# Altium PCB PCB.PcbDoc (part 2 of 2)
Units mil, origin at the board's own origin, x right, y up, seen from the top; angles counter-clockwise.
Board outline 1141.73 x 1220.47 mil, 2 copper layers (Top Layer, Bottom Layer), stack 61.8 mil thick; 114 components, 66 nets, 300 pads, 104 vias.
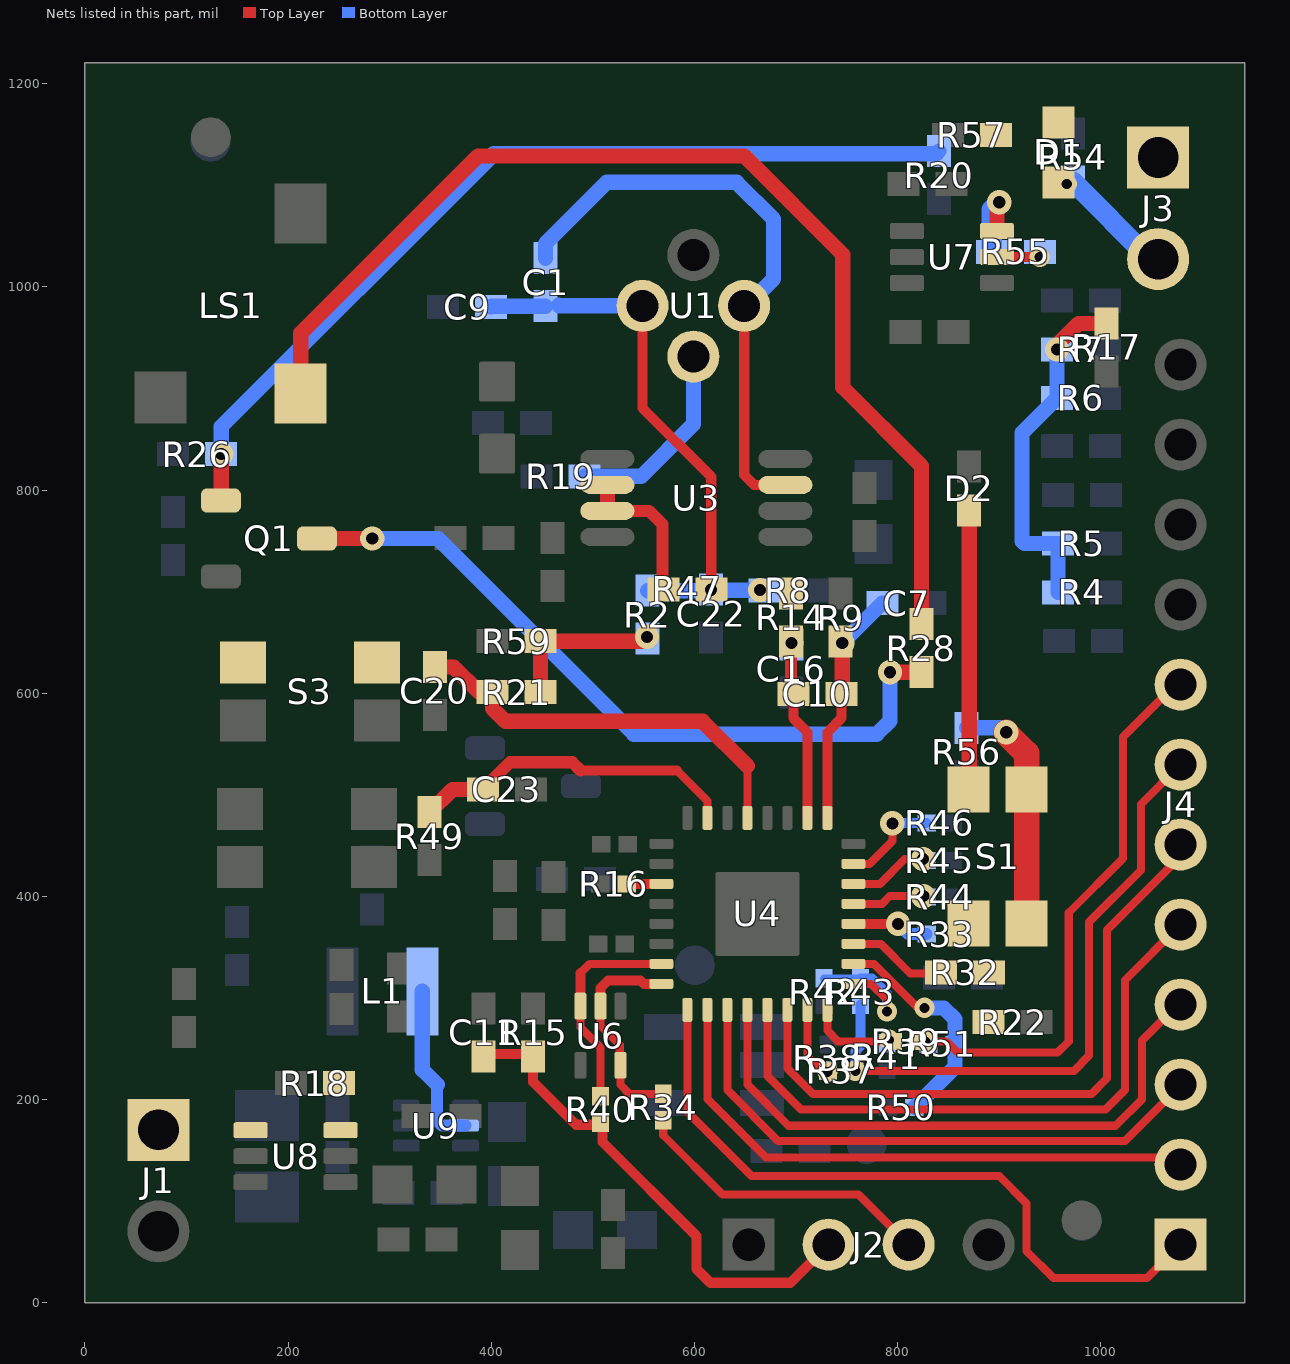
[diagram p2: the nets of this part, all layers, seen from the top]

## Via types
v1: diameter 24, hole 12, Top Layer to Bottom Layer, 83 vias
v2: diameter 20, hole 10, Top Layer to Bottom Layer, 9 vias
v3: diameter 40, hole 20, Top Layer to Bottom Layer, 6 vias
v4: diameter 19.68, hole 7.87, Top Layer to Bottom Layer, 5 vias
v5: diameter 24, hole 15, Top Layer to Bottom Layer, 1 vias

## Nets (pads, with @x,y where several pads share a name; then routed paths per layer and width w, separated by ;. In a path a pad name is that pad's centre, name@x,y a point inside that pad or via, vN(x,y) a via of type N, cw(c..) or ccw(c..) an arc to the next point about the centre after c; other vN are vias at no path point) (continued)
NetD1_1: D1.1 J3.1 R55.2 R57.1 U7.6 | length 81.3
  Top Layer w15: U7.6@897.66,1054.98 897.66,1081.08 v1(899.95,1083.36)
  Bottom Layer w20: R55.2@892.63,1034.39 892.63,1076.04 v1(899.95,1083.36)
NetD1_2: D1.2 J3.2 R54.2 | length 115.6
  Bottom Layer w20: R54.2@972.37,1103.77 1048.75,1027.39 J3.2@1056.37,1027.39
  other v2: 966.41,1101.37
NetJ1_1: J1.1 U8.1
NetL1_1: L1.1 U9.5 | length 163.4
  Bottom Layer w11.8: 346.75,214.87 346.75,179.03 351.39,174.39 U9.5@374.5,174.39
  Bottom Layer w15: L1.1@332.12,306.74 332.12,229.51 346.75,214.87
NetLS1_1: LS1.1 R28.1 | length 1081.1
  Top Layer w15: LS1.1@212.36,915.22 212.36,954.31 386.84,1128.79 649.09,1128.79 745.87,1032.01 745.87,901.25 823.37,823.75 R28.1@823.37,668.01
NetQ1_1: Q1.1 R20.1 R26.2 | length 891.9
  Top Layer w15: Q1.1@133.82,789.79 134.16,790.13 v1(134.16,835.53)
  Bottom Layer w15: v1(134.16,835.53) 134.16,862.65 402.48,1130.97 837.99,1130.97 R20.1@840.75,1133.73
NetQ1_3: Q1.3 R28.2 | length 728.2
  Top Layer w15: Q1.3@228.31,752.39 v1(282.75,752.39) ; v1(792.37,620.77) R28.2@823.37,620.77
  Bottom Layer w15: v1(282.75,752.39) 347.67,752.39 540.26,559.79 779.37,559.79 792.37,572.79 v1(792.37,620.77)
NetR2_2: R2.2 R21.1 R59.2 | length 156.5
  Top Layer w15: R21.1@448.5,601.27 R59.2@448.5,651.27 548.96,651.27 v1(553.2,655.51)
NetR4_2: R4.2 R5.2 R6.2 R7.2 R17.1 | length 349.4
  Top Layer w15: v1(956.75,938.39) 956.75,942.99 977.83,964.08 R17.1@1005.54,964.08
  Bottom Layer w15: v1(956.75,938.39) R6.2@956.75,890.74 922.36,856.35 922.36,749.7 924.67,747.39 R5.2@957.75,747.39 R4.2@957.75,699.39
NetR16_2: R16.2 U4.11 | length 36
  Top Layer w8: R16.2@531.36,412.39 R16.2@531.4,412.43
  Top Layer w9.8: R16.2@531.4,412.43 U4.11@567.35,412.43
NetR18_1: R18.1 U8.6
NetR32_2: R32.2 U4.27 | length 98.6
  Top Layer w8: U4.27@756.33,353.38 783.39,353.38 812.37,324.39 842.23,324.39 R32.2@842.75,324.91
NetR33_1: R33.1 U4.28 | length 78.2
  Top Layer w9.8: U4.28@756.33,373.06 v1(800.32,373.06) v1@802.32,373.06
  Bottom Layer w12: v1(800.32,373.06) 810.37,363.02 R33.1@828.38,363.02
NetR37_1: R37.1 R38.1 U4.23 | length 72.4
  Top Layer w8: U4.23@711.37,288.1 U4.23@711.06,288.42 711.06,242.71 725.37,228.39 R37.1@731.37,228.39
  other v2: 730.87,227.39
NetR39_1: R39.1 R41.1 U4.24 | length 89.4
  Top Layer w8: U4.24@730.74,288.42 730.74,268.02 741.37,257.39 R39.1@795.33,257.39
  other v2: 791.33,258.89
NetR42_1: R42.1 R43.1 U4.25 | length 139.7
  Top Layer w8: U4.25@756.33,314.01 773.76,314.01 789.37,298.39 v2(789.37,286.89) v2@789.37,285.39
  Bottom Layer w8: R42.1@727.37,319.39 R43.1@763.37,319.39 ; v2@789.37,285.39 v2(789.37,286.89)
  Bottom Layer w10: R43.1@763.37,319.39 774.38,319.39 789.37,304.39 v2(789.37,286.89)
NetR44_1: R44.1 U4.29 | length 75.2
  Top Layer w8: U4.29@756.33,392.75 784.53,392.75 792.17,400.39 v1(825.13,400.39)
  Bottom Layer w8: v1(825.13,400.39) R44.1@828.38,400.39
NetR45_1: R45.1 U4.30 | length 80.8
  Top Layer w8: U4.30@756.33,412.43 782.41,412.43 806.92,436.94 v1(824.93,436.94)
  Bottom Layer w8: R45.1@826.93,436.94 R45.1@828.38,438.39
NetR46_1: R46.1 U4.31 | length 102.7
  Top Layer w8: U4.31@756.33,432.12 772.09,432.12 794.72,454.75 v1(794.72,472.02)
  Bottom Layer w8: v1(794.72,472.02) v1@799.35,467.39
  Bottom Layer w10: v1@799.35,467.39 804.35,472.39 R46.1@828.38,472.39
NetR47_1: R47.1 U3.6 U3.7 | length 149.5
  Top Layer w10: R47.1@568.37,703.27 R47.1@569.25,702.39
  Top Layer w12: U3.7@514.27,779.6 555.17,779.6 568.37,766.39 R47.1@568.37,703.27
  Top Layer w15: U3.7@514.27,779.6 U3.6@514.27,805.19
NetR50_1: R50.1 R51.1 U4.26 | length 226
  Top Layer w8: U4.26@756.33,333.69 776.75,333.69 820.05,290.39 v2(826.37,290.39)
  Bottom Layer w15: R50.1@816.35,192.39 856.33,232.37 R51.1@856.33,254.39 856.33,279.39 845.33,290.39 v2(826.37,290.39)
NetR55_1: R55.1 U7.5 | length 42.2
  Top Layer w10: U7.5@897.66,1029.39 v2(939.87,1029.39)
NetR56_1: R56.1 S1.2 S1.4 | length 238.2
  Top Layer w25: v1(906.76,561.62) 906.76,561.01 926.91,540.87 S1.4@926.91,505.34 S1.2@926.91,373.45
  Bottom Layer w15: R56.1@867.79,566.01 901.76,566.01 v1@906.76,561.01
  Bottom Layer w20: v1@906.76,561.01 v1(906.76,561.62)
NTC+: R19.1 U1.2 | length 194.7
  Bottom Layer w15: R19.1@491.86,813.64 547.61,813.64 598.87,864.89 U1.2@598.87,931.39
ON/OFF: D2.2 R22.2 R32.1 S1.1 S1.3 | length 277.8
  Top Layer w8: R32.1@889.99,324.91 R32.1@889.99,327.77
  Top Layer w12: S1.3@869.83,505.34 S1.3@870.37,505.88
  Top Layer w15: S1.3@870.37,505.88 D2.2@870.37,780.09
RESET: C11.1 J2.2 R15.1 R40.1 | length 490.8
  Top Layer w10: C11.1@395.31,245.1 R15.1@441.05,245.1 ; R15.1@441.05,242.37 441.05,217.72 483.36,175.4 505.37,175.4 R40.1@507.37,177.4 509.37,175.4 509.37,158.39 601.79,65.98 601.79,33.6 615.58,19.8 694.41,19.8 J2.2@732,57.39 J2.2@732,58.76
RST: R40.2 U4.15 U6.3 | length 207.8
  Top Layer w8: U6.3@487.69,287.15 487.69,271.03 507.37,251.35 R40.2@507.37,203.39 ; 487.69,324.56 496.82,333.69 U4.15@567.35,333.69
  Top Layer w9.8: U6.3@487.69,292.15 487.69,324.56
SEG0: J4.1 U4.17 | length 694.8
  Top Layer w8: U4.17@592.94,288.42 592.94,187.82 656,124.76 899.95,124.76 926.91,97.79 926.91,50.83 953.22,24.52 1045.5,24.52 J4.1@1078.37,57.39
SEG1: J4.2 U4.18 | length 595
  Top Layer w8: U4.18@612.63,288.42 612.63,200.63 670.17,143.09 1062.41,143.09 1069.37,136.13 J4.2@1078.37,136.13 ; J4.2@1062.67,151.39 1069.37,144.69 J4.2@1069.37,139.39
SEG2: J4.3 U4.19 | length 574.4
  Top Layer w8: U4.19@632.32,288.42 632.32,209.41 682.33,159.39 1023.89,159.39 1078.37,213.87 J4.3@1078.37,214.87 ; J4.3@1069.37,218.39 J4.3@1069.37,223.43
SEG3: J4.4 U4.20 | length 600.1
  Top Layer w8: U4.20@652,288.42 652,214.85 692.45,174.39 1014.37,174.39 1040.37,200.39 1040.37,258.39 1075.59,293.61 J4.4@1078.37,293.61
SEG4: J4.5 U4.21 | length 624
  Top Layer w8: U4.21@671.69,288.42 671.69,223.35 704.64,190.39 1004.37,190.39 1023.6,209.63 1023.6,317.59 J4.5@1078.37,372.35
SEG5: J4.6 U4.22 | length 649
  Top Layer w8: U4.22@691.37,288.42 691.37,230.92 716.57,205.72 990.7,205.72 1006.13,221.15 1006.13,367.15 1078.37,439.39 J4.6@1078.37,451.09
SEG6: J4.7 R37.2 R43.2 | length 627.1
  Top Layer w8: v2(758.33,228.39) 973.37,228.39 988.37,243.39 988.37,374.9 1039.37,425.9 1039.37,490.83 J4.7@1078.37,529.83
  Bottom Layer w10: v2(758.33,228.39) 758.33,247.77 763.37,252.81 R43.2@763.37,293.4
SEG7: J4.8 R39.2 R51.2 | length 555.7
  Top Layer w8: R39.2@821.31,257.39 v2(827.34,257.39) 848,257.39 859,246.39 957.37,246.39 968.37,257.39 968.37,384.02 1021.84,437.49 1021.84,556.87 1073.55,608.57 J4.8@1078.37,608.57
TEST: J2.3 R34.1 | length 300.8
  Top Layer w8: R34.1@569.25,179.74 569.25,165.06 627.52,106.79 761.34,106.79 J2.3@810.74,57.39
TP+: C1.1 U1.1 U3.3 | length 588.4
  Top Layer w10: U1.1@648.87,981.39 648.87,814.89 658.57,805.19 U3.3@689.47,805.19
  Bottom Layer w15: C1.1@453.43,1028.24 453.43,1042.86 513.52,1102.95 641.49,1102.95 677.62,1066.82 677.62,1007.96 651.06,981.39 U1.1@648.87,981.39
TP-: C1.2 C9.1 C22.1 R2.1 R8.1 R14.1 R47.2 U1.3 | length 560.6
  Top Layer w10: U1.3@548.87,981.39 548.87,880.69 616.49,813.07 R47.2@616.49,702.39
  Bottom Layer w15: C9.1@399.77,980.31 400.46,981 C1.2@453.43,981 ; 466.17,982.02 466.8,981.39 U1.3@548.87,981.39 ; R2.1@553.62,701.01 615.37,701.01 v1(616.37,702.01) 616.99,701.39 R8.1@668.75,701.39 R8.1@668.13,702.01
  other v1: 664.44,701.7
TST: R34.2 U4.16 U6.2 U6.5 | length 213.9
  Top Layer w8: U6.2@507.37,287.15 507.37,272.8 526.37,253.8 526.37,229.57 U6.5@527.06,228.88 ; U6.5@527.06,233.88 U6.5@527.06,228.88 ; R34.2@569.25,205.72 536.03,205.72 527.06,214.7 U6.5@527.06,228.88
  Top Layer w9.8: U6.2@507.37,292.15 507.37,310.08 514.76,317.48 546.83,317.48 550.3,314.01 U4.16@567.35,314.01
V_BATT_ADCin: C23.1 R49.2 U4.7 | length 326
  Top Layer w8: 582.66,524.02 612.63,494.05 U4.7@612.63,477.39
  Top Layer w10: 487.69,524.02 582.66,524.02
  Top Layer w12: C23.1@391.75,505.34 418.49,532.08 479.62,532.08 487.69,524.02
  Top Layer w15: R49.2@339.37,483.02 361.69,505.34 C23.1@391.75,505.34
V_TP+: C7.1 C10.1 R9.2 U4.1 | length 234.1
  Top Layer w9.8: U4.1@730.74,477.39 730.74,561.76 744.49,575.51 C10.1@744.49,599.39 C10.1@745.37,600.27
  Top Layer w15: C10.1@745.37,600.27 v1(745.37,649.39)
  Bottom Layer w15: v1(745.37,649.39) 784.75,688.77 C7.1@785.13,688.77
V_TP-: C10.2 C16.1 R14.2 U4.2 | length 180.1
  Top Layer w8: C10.2@695.37,601.27 C10.2@697.25,599.39
  Top Layer w9.8: C10.2@697.25,599.39 697.25,575.51 711.06,561.71 U4.2@711.06,477.39
  Top Layer w12: R14.2@694.87,650.77 694.87,601.77 C10.2@695.37,601.27
  other v1: 695.37,649.39
VREF1_ADC: C20.1 R21.2 S3.2 S3.4 U4.5 | length 408.6
  Top Layer w8: U4.5@652,477.39 652,528.39
  Top Layer w15: C20.1@344.37,626.01 362.93,626.01 387.67,601.27 R21.2@401.25,601.27 401.25,584.98 413.84,572.39 608,572.39 652,528.39
pads on no net: FID1.1 FID2.1 FID4.1 FID5.1 LS1.3 U4.33@639.4,360.46 U4.33@639.4,405.35 U4.33@684.28,360.46 U4.33@684.28,405.35 U6.1 U7.4
copper on no net: | length 6.4
  Bottom Layer w8: 553.62,600.52 553.75,600.39
  Bottom Layer w15: 553.75,600.39 553.75,602.39 553.75,604.27 555.37,605.89

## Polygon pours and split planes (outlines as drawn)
AVSS on Bottom Layer "BOTTOM_LAYER_AVSS_P080" (solid, remove dead copper, pour order 80): 1.14,1220.15 1133.97,1220.15 1141.2,1212.92 1141.2,9.72 1129.24,-2.24 18.19,-2.24 0.81,15.14 0.81,1218.82 1.22,1219.23
BATT_PLUS on Bottom Layer "BOTTOM_LAYER_BATT_PLUS_P000" (solid, remove dead copper, pour order 0): 276.56,174.39 290.49,188.32 329.3,188.32 329.3,200.39 283.37,200.39 274.37,209.39 274.37,278.39 273.37,279.39 274.37,280.39 274.37,333.18 260.36,347.18 183.16,347.18 142.37,306.39 142.37,160.39 141.87,159.89 141.87,158.89 145.37,155.39 208.37,155.39 212.37,159.39 212.37,171.39 215.37,174.39
NetC5_1 on Bottom Layer "BOTTOM_LAYER_NETC5_1_P042" (solid, remove dead copper, pour order 42): 307.37,160.39 294.37,147.39 293.2,147.39 284.83,139.03 284.83,82.93 292.37,75.39 316.24,75.39 327.48,86.63 327.48,142.5 332.87,147.89 332.87,156.39 328.87,160.39
3V3 on Bottom Layer "BOTTOM_LAYER_3V3_P020" (solid, remove dead copper, pour order 20): 940.37,759.39 940.37,690.27 948.33,682.31 968.41,682.31 976.37,690.27 976.37,761.05 942.03,761.05
3V3 on Bottom Layer "BOTTOM_LAYER_3V3_P016" (solid, remove dead copper, pour order 16): 799.31,1101.37 854.36,1101.37 854.36,1071.22 821.2,1071.22 779.37,1029.39 779.37,938.39 786.37,931.39 909.15,931.39 909.15,875.39 772.69,875.39 734.37,913.71 734.37,1108.58 740.05,1114.26 786.42,1114.26
NetC8_1 on Bottom Layer "BOTTOM_LAYER_NETC8_1_P012" (solid, remove dead copper, pour order 12): 396.37,437.39 467.97,437.39 471,434.36 471,406.02 467.37,402.39 396.37,402.39 394.37,404.39 394.37,435.39
NetC3_1 on Bottom Layer "BOTTOM_LAYER_NETC3_1_P002" (solid, remove dead copper, pour order 2): 436.37,133.39 474.24,133.39 496.54,111.08 496.54,50.22 456.96,50.22 447.37,59.8 447.37,81.39 439.37,89.39 346.37,89.39 340.37,95.39 339.37,122.89 339.37,143.71 356.05,160.39 386.37,160.39 390.47,156.29 390.47,141.29 398.37,133.39
AVSS on Top Layer "TOP_LAYER_AVSS_P076" (solid, remove dead copper, pour order 76): 1.14,1220.15 1133.97,1220.15 1141.2,1212.92 1141.2,9.72 1129.24,-2.24 18.19,-2.24 0.81,15.14 0.81,1218.82 1.22,1219.23
no net on Top Layer "TOP_LAYER_NONET_P072" (solid, remove dead copper, pour order 72): 422.76,602.08 436.53,588.31 512.21,588.31 519.87,595.98 519.87,619.4 518.5,620.77 482.83,620.77 461.43,642.17 461.43,660.46 422.76,660.46
3V3 on Top Layer "TOP_LAYER_3V3_P070" (solid, remove dead copper, pour order 70): 859.82,1179.95 755.33,1179.95 741.37,1165.99 741.37,1059.48 754.51,1046.35 821.95,1046.35 824.37,1048.77 824.37,1115.3 835.68,1126.61 862.72,1126.61 867.07,1130.97 867.07,1165.42 867.07,1172.7
NetD1_1 on Top Layer "TOP_LAYER_NETD1_1_P068" (solid, remove dead copper, pour order 68): 1092.73,1143.04 1092.73,1165.81 1078.59,1179.95 894.45,1179.95 880.49,1165.99 880.49,1051.27 885.5,1046.26 998.72,1046.26 1028.83,1076.37 1081.37,1076.37 1081.37,1077.16 1093.78,1089.57
BATT_PLUS on Top Layer "TOP_LAYER_BATT_PLUS_P056" (solid, remove dead copper, pour order 56): 94.03,284.71 124.69,284.71 139.2,299.22 209.26,299.22 214.98,293.51 214.98,204.18 190.2,204.18 162.74,231.64 89.07,231.64 80.83,239.88 80.83,279.37
NetC4_2 on Top Layer "TOP_LAYER_NETC4_2_P048" (solid, remove dead copper, pour order 48): 664.84,762.39 741.37,762.39 750.37,771.39 779.37,771.39 780.37,770.39 780.37,739.39 758.37,717.39 758.37,684.39 754.37,680.39 732.37,680.39 730.37,682.39 730.37,728.39 715.37,743.39 664.84,743.39 661.84,746.39 661.84,759.39
TP- on Top Layer "TOP_LAYER_TP-_P046" (solid, remove dead copper, pour order 46): 575.4,641.87 576.74,640.53 640,640.53 679.87,680.39 710.06,680.39 711.06,681.39 711.06,709.39 705.46,714.99 605.97,714.99 600.37,709.39 600.37,687.31 589.79,676.73 578.02,676.73 575.4,674.11
NetJ1_1 on Top Layer "TOP_LAYER_NETJ1_1_P044" (solid, remove dead copper, pour order 44): 179.5,161.39 127.37,161.39 108.37,142.39 40.98,142.39 40.98,193.37 62,214.39 159.08,214.39 179.5,193.97
NetC3_1 on Top Layer "TOP_LAYER_NETC3_1_P038" (solid, remove dead copper, pour order 38): 446.69,136.39 446.69,96.38 439.7,89.39 346.37,89.39 339.37,96.39 339.37,149.39 342.37,152.39 379.37,152.39 395.37,136.39
NetR18_1 on Top Layer "TOP_LAYER_NETR18_1_P036" (solid, remove dead copper, pour order 36): 234.37,231.39 264.22,231.39 270.37,225.25 270.37,162.39 232.37,162.39 231.37,163.39 231.37,228.39
ON/OFF on Top Layer "TOP_LAYER_ON/OFF_P032" (solid, remove dead copper, pour order 32): 849.37,528.39 848.37,527.39 848.37,356.9 854.88,350.39 860.37,350.39 873.78,336.99 873.78,265.99 904.78,265.99 906.37,264.39 906.37,336.39 891.37,351.39 891.37,527.39 890.37,528.39
NetC21_1 on Top Layer "TOP_LAYER_NETC21_1_P030" (solid, remove dead copper, pour order 30): 350.99,377.17 347.09,373.27 272.26,373.27 257.7,392.76 138.01,392.76 127.37,403.39 120.34,410.42 120.34,443.36 127.37,450.39 348.72,450.39 350.99,448.13
VREF1_ADC on Top Layer "TOP_LAYER_VREF1_ADC_P028" (solid, remove dead copper, pour order 28): 358.69,658.57 371.75,645.51 371.75,611.71 130.06,611.71 127.37,614.39 127.37,651.27 134.67,658.57

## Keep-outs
Keep-Out Layer:
  text ".Layer_Name" at 616.37,-839.1 h60

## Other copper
Top Layer:
  region net NetC17_1: 792.37,942.39 791.37,943.39 791.37,1010.39 793.37,1012.39 825.37,1012.39 827.37,1010.39 827.37,945.39 824.37,942.39
  region: 842.23,519.39
  region net NetC8_1: 400.37,435.39 402.37,437.39 472.37,437.39 475.37,434.39 475.37,404.39 473.37,402.39 402.37,402.39 400.37,404.39
  region: 107.37,650.64
  region: 554.37,75.39
  region: 49.37,19.39
  region: 598.37,192.39
  region: 592.94,288.42
  text ".Layer_Name" at 616.37,-839.1 h60
Bottom Layer:
  region net 3V3: 569.36,194.23
  region net AVSS: 937.37,276.39
  region: 940.37,764.39
  region net NetC8_1: 470.87,416.89
  region net NetC8_1: 468.87,403.89
  region: 590.37,670.39
  region: 340.37,95.39
  region net NetC5_1: 321.37,160.39
  region: 292.37,159.39
  region: 800.37,290.39
  region: 614.87,75.39
  text ".Layer_Name" at 616.37,-839.1 h60

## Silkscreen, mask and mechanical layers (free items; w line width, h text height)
Top Overlay:
  lines w6: 99.44,592.92 117.59,592.92 ; 107.67,669.39 288.87,669.39 300.48,657.79 347.09,657.79 358.69,669.39 361.85,669.39 ; 201.37,351.41 212.37,351.41 231.35,370.39 307.08,370.39 309.95,373.27 375.76,373.27 ; 319.53,213.5 319.53,244.4 ; 319.53,795.58 433.34,795.58 440.87,788.05 ; 335.37,154.5 448.97,154.5 470.11,175.65 470.11,227.39 ; 371.75,330.34 407.37,330.34 ; 460.1,332.98 469.97,323.12 469.97,307.89 ; 502.42,471.31 502.42,518.95 509.31,525.84 524.49,525.84 ; 548.87,96.76 835.4,96.76 ; 562.43,244.4 567.87,244.4 ; 592.57,681.39 604.57,669.39 617.87,669.39 ; 598.87,195.89 630.35,195.89 ; 781.37,716.84 848.87,716.84 ; 841.37,247.71 851.29,237.79 868.37,237.79 ; 299.37,1063.39 301.23,1061.53 335.37,1027.39 349.61,1013.15 477.75,1013.15 477.75,1023.66 502.42,1048.33 502.42,1068.48 502.42,1147.32 492.79,1156.95 374.24,1156.95 312.62,1156.95 299.37,1143.7 299.37,1063.39 ; 344.37,1086.32 344.37,1086.32
  text "A" at 350.99,1023.18 h30
  text "A" at 344.37,264.09 h30
  text ".Layer_Name" at 616.48,-840.04 h60
Bottom Overlay:
  lines w6: 69.28,223.18 80.67,211.79 129.25,211.79 ; 448.92,671.89 522.89,671.89 ; 695.37,127.39 710.37,112.39 758.33,112.39 ; 707.3,228.39 707.3,273.32 767.37,273.32 ; 802.37,173.37 823.61,152.13 866.38,152.13 873.07,158.82 ; 839.37,273.32 873.91,273.32 ; 932.37,173.37 1000.35,173.37 1030.37,203.39 1030.37,223.26 ; 964.25,286.89 1019.87,286.89 1030.37,276.39
  text "'.PRJ_Number'.PCB_Rev" at 710.37,812.39 h35
  text "C2" at 97.69,237.29 h30 r270
  text ".Layer_Name" at 616.37,-839.1 h60
Top Paste:
  text ".Layer_Name" at 616.37,-839.1 h60
Bottom Paste:
  text ".Layer_Name" at 616.37,-839.1 h60
Top Solder:
  text ".Layer_Name" at 616.37,-839.1 h60
  text ".Layer_Name" at 616.37,-839.1 h60
Bottom Solder:
  text ".Layer_Name" at 616.37,-839.1 h60
Drill Guide:
  text ".Layer_Name" at 616.37,-839.1 h60
M1 Board Outline:
  the board outline again, w10
  text ".Layer_Name" at 758.7,-823.61 h60
M2 Board Dimensions:
  rectangle: 39.37,-255.61 164.37,-130.61
  rectangle: 164.37,-380.61 539.37,-255.61
  lines w7: 39.37,-255.61 1039.37,-255.61 ; 164.37,-380.61 164.37,-130.61 ; 289.37,-380.61 289.37,-130.61 ; 539.37,-380.61 539.37,-130.61 ; 789.37,-380.61 789.37,-130.61 ; 39.37,-380.61 1039.37,-380.61 1039.37,-130.61 39.37,-130.61 39.37,-380.61
M3 3D STEP Top:
  text ".Layer_Name" at 616.37,-839.1 h60
M4 3D STEP Bottom:
  text ".Layer_Name" at 616.37,-839.1 h60
M5 Assembly Top:
  lines w10: -252.63,-910.77 6347.37,-910.77 ; -252.63,-707.44 6349.37,-707.44 ; -252.63,-504.11 -252.63,-1114.11 3752.37,-1114.11 6349.37,-1114.11 6349.37,-504.11 -252.13,-504.11 -252.13,-1114.11 1323.37,-1114.11 ; 2212.37,-1114.11 2212.37,-504.11 ; 3479.37,-707.44 3479.37,-504.11 ; 4319.37,-707.44 4319.37,-504.11 ; 4941.37,-1120.61 4941.37,-917.77
  text "COMPONENTS MARKED 'DNP' SHOULD NOT BE POPULATED." at 1192.87,-299.11 h60
  text "ASSEMBLY VARIANT:" at 1192.37,-414.61 h60
  text ".VariantName" at 2228.37,-414.61 h60
  text "PCB VIEWED FROM TOP SIDE" at -189.13,-636.27 h60
  text "REV:" at 3677.37,-636.27 h60
  text ".PCB_Rev" at 3968.87,-636.27 h60
  text "SVN REV:" at 4515.37,-636.27 h60
  text ".VersionControl_RevNumber" at 5021.37,-636.27 h60
  text "BOARD #:" at 2228.37,-645.4 h60
  text ".PRJ_Number" at 2679.88,-655.18 h60
  text ".Layer_Name" at 898.07,-820.09 h60
  text "Layer Name =" at 26.76,-836.61 h60
  text "TID #:" at 2287.37,-839.61 h60
  text ".TID" at 2832.87,-839.61 h60
  text "PLOT NAME =" at -189.13,-1044.94 h60
  text "GENERATED    :" at 2289.37,-1044.94 h60
  text ".Print_Date" at 3158.87,-1044.94 h60
  text ".Print_Time" at 3887.87,-1044.94 h60
  text "TEXAS INSTRUMENTS" at 5152.37,-1044.94 h60
  text ".plot_File_Name" at 467.65,-1051.5 h60
M6 Assembly Bottom:
  lines w10: -253.13,-707.94 6348.87,-707.94 ; -251.13,-911.27 6348.87,-911.27 ; 1154.87,-1121.11 1154.87,-918.27 ; 1776.87,-707.94 1776.87,-504.61 ; 2616.87,-707.94 2616.87,-504.61 ; 3883.87,-1114.61 3883.87,-504.61 ; 4772.87,-1114.61 6348.37,-1114.61 6348.37,-504.61 -253.13,-504.61 -253.13,-1114.61 2343.87,-1114.61 6348.87,-1114.61 6348.87,-504.61
  text "COMPONENTS MARKED 'DNP' SHOULD NOT BE POPULATED." at 6141.37,-298.61 h60
  text ".VariantName" at 5097.37,-414.61 h60
  text "ASSEMBLY VARIANT:" at 6136.37,-414.61 h60
  text "BOARD #:" at 3870.49,-621.04 h60
  text ".PRJ_Number" at 3420.05,-621.96 h60
  text ".VersionControl_RevNumber" at 1074.87,-636.77 h60
  text "SVN REV:" at 1580.87,-636.77 h60
  text ".PCB_Rev" at 2127.37,-636.77 h60
  text "REV:" at 2418.87,-636.77 h60
  text "PCB VIEWED FROM BOTTOM SIDE" at 6285.37,-636.77 h60
  text ".Layer_Name" at 5206.85,-834.48 h60
  text ".TID" at 3263.37,-840.11 h60
  text "TID #:" at 3808.87,-840.11 h60
  text "Layer Name =" at 6161.03,-850.85 h60
  text "TEXAS INSTRUMENTS" at 943.87,-1045.44 h60
  text ".Print_Time" at 2208.37,-1045.44 h60
  text ".Print_Date" at 2937.37,-1045.44 h60
  text "GENERATED    :" at 3806.87,-1045.44 h60
  text "PLOT NAME =" at 6285.37,-1045.44 h60
  text ".plot_File_Name" at 5617.77,-1048.71 h60
M9 Title Sheet:
  drawing of 57 lines, arcs and shapes, not listed
  text "1" at 779.21,8055.89 h70
  text "2" at 3274.87,8055.89 h70
  text "3" at 5764.21,8055.89 h70
  text "4" at 8270.88,8055.89 h70
  text "5" at 10769.87,8055.89 h70
  text "6" at 13274.87,8055.89 h70
  text "A" at -377.13,6912.89 h70
  text "A" at 14422.87,6912.89 h70
  text "B" at -377.13,4532.89 h70
  text "B" at 14422.87,4532.89 h70
  text "C" at -377.13,2157.89 h70
  text "C" at 14422.87,2157.89 h70
  text "PROJECT TITLE:" at 11382.87,296.89 h45
  text ".PRJ_Title" at 11432.87,163.57 h70
  text "DESIGNED FOR:" at 11382.87,-4.11 h45
  text ".PRJ_Customer" at 11432.87,-144.11 h70
  text "D" at -377.13,-212.11 h70
  text "D" at 14422.87,-212.11 h70
  text "FILE NAME:" at 11382.87,-304.11 h45
  text ".PCB_File_Name_No_Path" at 11432.87,-424.11 h70
  text "Texas Instruments (TI) and/or its licensors do not warrant the accuracy or completeness of this specification" at 6413.37,-585.95 h45
  text "ENGINEER:" at 11382.87,-594.11 h45
  text "LAYOUT BY:" at 12887.87,-594.11 h45
  text "or any information contained therein. TI and/or its licensors do not warrant that this design will meet" at 6368.38,-698.61 h45
  text ".PRJ_Engineer" at 11432.87,-749.1 h70
  text ".PCB_Layout" at 12938.37,-749.1 h70
  text "the specifications, will be suitable for your application or fit for any particular purpose, or will operate in" at 6368.38,-811.28 h45
  text "ALTIUM DESIGNER VERSION:" at 12887.87,-904.11 h45
  text "an implementation. TI and/or its licensors do not warrant that the design is production worthy. You should" at 6368.38,-923.94 h45
  text "completely validate and test your design implementation to confirm the system functionality for your application." at 6413.37,-1036.61 h45
  text ".print_Scale" at 11432.87,-1037.43 h70
  text ".Application_BuildNumber" at 12938.37,-1037.43 h70
  text "1" at 779.21,-1244.11 h70
  text "2" at 3274.87,-1244.11 h70
  text "3" at 5764.21,-1244.11 h70
  text "4" at 8270.88,-1244.11 h70
  text "5" at 10769.87,-1244.11 h70
  text "6" at 13274.87,-1244.11 h70
M10 Fab Notes:
  drawing of 189 lines, arcs and shapes, not listed
  text "DESIGN INFORMATION" at 12421.39,6375.57 h60
  text "MIN. TRACK WIDTH:" at 11776.83,6243.44 h60
  text "8" at 12873.07,6243.44 h60
  text "MIL" at 13027.83,6243.44 h60
  text "MIN. CLEARANCE:" at 11776.83,6119.31 h60
  text "MIL" at 13027.83,6119.31 h60
  text "6.1" at 12821.86,6117.51 h60
  text "MIN. VIA PAD SIZE:" at 11776.83,5995.19 h60
  text "MIL" at 13027.83,5995.19 h60
  text "19.685" at 12658.55,5991.03 h60
  text "0.05mm (2MIL)" at 12471.83,5865.29 h60
  text "MINIMUM ANNULAR RING" at 11447.6,5857.07 h60
  text "EXTERNAL" at 13179.83,5857.07 h60
  text "PER" at 11647.6,5746.94 h60
  text "IPC-D-275 CLASS 2 LEVEL C" at 11867.6,5746.94 h60
  text "MIL, HOLES" at 13355.83,5646.46 h60
  text "+/-" at 12963.37,5637.88 h60
  text "+/-" at 13817.37,5637.88 h60
  text "REGISTRATION TOLERANCES:" at 11447.6,5636.81 h60
  text "METAL" at 12647.37,5636.81 h60
  text "5" at 13223.57,5636.81 h60
  text "3" at 14056.57,5636.81 h60
  text "MIL" at 14172.83,5636.81 h60
  text "HOLE SIZE TOLERANCE (UNLESS OTHERWISE SPECIFIED):" at 11447.6,5538.5 h60
  text "+/-" at 13817.37,5535.62 h60
  text "3" at 14056.57,5534.56 h60
  text "MIL" at 14172.83,5534.56 h60
  text "MATERIAL:" at 11372.83,5396.91 h60
  text "FR-4 High Tg" at 12359.27,5268.39 h60
  text "X" at 12214.83,5260.4 h60
  text "FR-408" at 11793.83,5255.88 h60
  text "OTHER" at 13281.83,5255.88 h60
  text "62 MIL (1.6mm) +/-10%" at 12113.93,5112.85 h60
  text "X" at 11993.83,5110.4 h60
  text "THICKNESS:" at 11447.6,5104.63 h60
  text "OTHER" at 13398.83,5104.63 h60
  text "TOLERANCE:" at 11447.6,4966.32 h60
  text "X" at 12295.83,4966.32 h60
  text "ANSI IPC-6012 TYPE 3 CLASS 2" at 12473.85,4966.32 h60
  text "OTHER +/-" at 12473.83,4822.13 h60
  text "BOW & TWIST:" at 11447.6,4676.94 h60
  text "X" at 12295.83,4676.94 h60
  text "ANSI IPC-6012 TYPE 3 CLASS 2" at 12473.85,4676.94 h60
  text "OTHER +/-" at 12473.83,4530.24 h60
  text "DRILLING:" at 11372.83,4399.62 h60
  text "NC_DRILL FILES" at 13133.83,4294.43 h60
  text "REFERENCE:" at 11447.6,4290.5 h60
  text "X" at 12104.83,4290.4 h60
  text "AS SHOWN" at 12282.83,4290.5 h60
  text "X" at 13005.83,4290.5 h60
  text "OTHER" at 13431.83,4148.24 h60
  text "PTH COPPER THICKNESS:" at 11447.28,4144.72 h60
  text "X" at 12586.51,4144.72 h60
  text "20-30 um" at 12714.51,4144.72 h60
  text "BOARD FINISH:" at 11372.83,3997.12 h60
  text "SILKSCREEN:" at 11528.05,3886.99 h60
  text "X" at 12485.83,3886.99 h60
  text "TOP" at 12602.83,3886.99 h60
  text "X" at 12995.83,3886.99 h60
  text "BOTTOM" at 13113.83,3886.99 h60
  text "SILKSCREEN COLOR:" at 11528.05,3731.8 h60
  text "X" at 12484.83,3731.8 h60
  text "WHITE" at 12602.83,3731.8 h60
  text "OTHER" at 13113.83,3731.8 h60
  text "X" at 12615.83,3588.36 h60
  text "GREEN" at 12733.83,3588.36 h60
  text "OTHER" at 13351.83,3588.36 h60
  text "SOLDER RESIST COLOR:" at 11528.05,3581.49 h60
  text "X" at 12615.83,3434.1 h60
  text "MATTE" at 12733.83,3434.1 h60
  text "SEMI-GLOSS" at 13351.37,3433.47 h60
  text "IMMERSION GOLD (ENIG)" at 12433.83,3261.33 h60
  text "ENEPIG" at 13771.37,3254.11 h60
  text "SURFACE FINISH:" at 11372.83,3253.11 h60
  text "X" at 12255.83,3253.11 h60
  text "IMM. TIN/SILVER OR EQUIV" at 11702.37,3115.8 h60
  text "OTHER" at 13133.83,3111.86 h60
  text "ARRAY/PANEL:" at 11372.83,2956.48 h60
  text "CUT AND TRIM PER M1 BOARD OUTLINE" at 12433.83,2948.26 h60
  text "N.C. ROUTE" at 12433.83,2812.29 h60
  text "X" at 13121.83,2812.29 h60
  text "V. SCORE" at 13299.83,2812.29 h60
  text "CERTIFICATION:" at 11372.83,2683.17 h60
  text "MATERIALS AND WORKMANSHIP FOR ALL PCBS" at 12097.83,2683.17 h60
  text "TO MEET OR EXCEED THE REQUIREMENTS OF:" at 12097.83,2589.1 h60
  text "X" at 11735.34,2460.47 h60
  text "ANSI IPC-A-600F CLASS ->" at 11863.33,2460.47 h60
  text "X" at 13511.34,2460.47 h60
  text "2" at 13621.33,2460.47 h60
  text "1" at 13306.33,2458.98 h60
  text "3" at 13975.33,2458.98 h60
  text "X" at 12547.34,2312.79 h60
  text "RoHS" at 12675.33,2312.79 h60
  text "OTHER" at 13319.73,2312.79 h60
  text "PER ORDER" at 13716.79,2312.79 h60
  text "ALL BOARDS MUST MEET OR EXCEED UL94-V0 REQUIREMENTS." at 11400.37,2158.96 h60
  text "PCB MUST BEAR THE UL94V-0 UL REGISTERED MATERIAL ID NUMBER" at 11400.37,2042.9 h60
  text "ADDITIONAL REQUIREMENTS:" at 11372.83,1873.47 h60
  text "MICROSECTION:" at 11447.6,1766.35 h60
  text "YES" at 12353.33,1766.35 h60
  text "REQUIRED" at 13214.83,1622.01 h60
  text "BARE BOARD ELEC. TEST:" at 11447.6,1619.16 h60
  text "NONE" at 12753.33,1619.16 h60
  text "X" at 13096.83,1619.16 h60
  text "PER ORDER" at 13806.83,1619.16 h60
  text "XX MIL VIAS REQUIRE NON-CONDUCTIVE FILL AND PLANARIZE" at 11615.75,1414.21 h59
  text "XX MIL VIAS REQUIRE CONDUCTIVE FILL AND PLANARIZE" at 11623.75,1310.24 h60
  text "OUTER XX MIL TRACES REQUIRE 50 OHM SINGLE-ENDED IMPEDANCE" at 11622.76,1146.85 h58
  text "LAYER 2 & 3 (INNER LAYERS) XX MIL WIDE, XX MIL SPACE / TRACES REQUIRE 100 OHM DIFFERENTIAL IMPEDANCE" at 11614.76,911.14 h60
  text "NOTE:" at 1673.47,882.49 h50
  text "1)THIS IS NOT AN IMPEDANCE CONTROLLED BOARD" at 1861.9,786.59 h50
  text "2)ALL VIAS ARE NON TENTED." at 1855.35,656.59 h50
  text "3) FOR ON PAD VIA'S FILLED WITH NON CONDUCTIVE MATERIAL AND CAP PLATING" at 1840.35,516.59 h50
  text "4)VENDOR MAY ADJUST SOLDERMASK WHEREVER SOLDERMASK PADS ARE SAME SIZE(1:1)" at 1850.35,376.59 h50
  text "AS PER MANUFACTURING CAPABILITIES AND ALL OTHER SOLDERMASK PADS SHALL NOT BE MODIFIED" at 1949.86,263.72 h50
  text "PROVIDED NO ADJACENT COPPER IS EXPOSED AND NO CONFLICT PRODUCED WITH ANY STATED" at 1949.86,162.72 h50
  text "\"VIA TENTING/COVERING\" REQUIREMENTS." at 1949.86,69.72 h50
M11 Gerber Information:
  lines w10: -252.63,-910.77 6347.37,-910.77 ; -252.63,-707.44 6349.37,-707.44 ; -252.63,-504.11 -252.63,-1114.11 3752.37,-1114.11 6349.37,-1114.11 6349.37,-504.11 -252.13,-504.11 -252.13,-1114.11 1323.37,-1114.11 ; 2212.37,-1114.11 2212.37,-504.11 ; 3479.37,-707.44 3479.37,-504.11 ; 4319.37,-707.44 4319.37,-504.11 ; 4941.37,-1120.61 4941.37,-917.77
  text "ALL ARTWORK VIEWED FROM TOP SIDE" at -189.13,-636.27 h60
  text "REV:" at 3677.37,-636.27 h60
  text ".PCB_Rev" at 3968.87,-636.27 h60
  text "SVN REV:" at 4515.37,-636.27 h60
  text ".VersionControl_RevNumber" at 5021.37,-636.27 h60
  text "BOARD #:" at 2229.47,-637.37 h60
  text ".PRJ_Number" at 2666.93,-647.49 h60
  text "LAYER NAME =" at -189.13,-839.1 h60
  text "TID #:" at 2287.37,-839.61 h60
  text ".TID" at 2832.87,-839.61 h60
  text "PLOT NAME =" at -189.13,-1044.94 h60
  text ".plot_File_Name" at 616.37,-1044.94 h60
  text "GENERATED    :" at 2289.37,-1044.94 h60
  text ".Print_Date" at 3158.87,-1044.94 h60
  text ".Print_Time" at 3887.87,-1044.94 h60
  text "TEXAS INSTRUMENTS" at 5152.37,-1044.94 h60
M12 Stackup:
  drawing of 191 lines, arcs and shapes, not listed
  text "Layer" at 2052.78,2134.6 h60
  text "Name" at 2462.69,2134.6 h60
  text "Material" at 3392.44,2134.6 h60
  text "Thickness" at 4252.2,2134.6 h60
  text "Constant" at 4902.04,2134.6 h60
  text "Board Layer Stack" at 5471.9,2134.6 h60
  text "1" at 2052.78,2014.6 h60
  text "Top Overlay" at 2462.69,2014.6 h60
  text "2" at 2052.78,1894.6 h60
  text "Top Solder" at 2462.69,1894.6 h60
  text "Solder Resist" at 3392.44,1894.6 h60
  text "0.40mil" at 4252.2,1894.6 h60
  text "3.5" at 4902.04,1894.6 h60
  text "3" at 2052.78,1774.6 h60
  text "Top Layer" at 2462.69,1774.6 h60
  text "Copper" at 3392.44,1774.6 h60
  text "1.40mil" at 4252.2,1774.6 h60
  text "4" at 2052.78,1654.6 h60
  text "Dielectric 2" at 2462.69,1654.6 h60
  text "FR-4 High TG" at 3392.44,1654.6 h60
  text "59.00mil" at 4252.2,1654.6 h60
  text "4.2" at 4902.04,1654.6 h60
  text "5" at 2052.78,1534.6 h60
  text "Bottom Layer" at 2462.69,1534.6 h60
  text "Copper" at 3392.44,1534.6 h60
  text "1.40mil" at 4252.2,1534.6 h60
  text "6" at 2052.78,1414.6 h60
  text "Bottom Solder" at 2462.69,1414.6 h60
  text "Solder Resist" at 3392.44,1414.6 h60
  text "0.40mil" at 4252.2,1414.6 h60
  text "3.5" at 4902.04,1414.6 h60
  text "7" at 2052.78,1294.6 h60
  text "Bottom Overlay" at 2462.69,1294.6 h60
M13 Component Bodies Top:
  text ".Layer_Name" at 616.37,-839.1 h60
M14 Component Bodies Bottom:
  text ".Layer_Name" at 616.37,-839.1 h60
M15 Courtyards Top:
  text ".Layer_Name" at 616.37,-839.1 h60
M16 Courtyards Bottom:
  text ".Layer_Name" at 616.37,-839.1 h60
Drill Drawing:
  circle w10: c4748.53,4089.94 r33.33
  lines w10: 4715.2,3473.28 4731.87,3473.28 4748.53,3456.61 4765.2,3473.28 4781.87,3473.28 4765.2,3489.94 4781.87,3506.61 4765.2,3506.61 4748.53,3523.28 4731.87,3506.61 4715.2,3506.61 4731.87,3489.94 4715.2,3473.28 ; 4715.2,3606.61 4715.2,3623.28 4731.87,3639.94 4715.2,3656.61 4715.2,3673.28 4731.87,3673.28 4748.53,3656.61 4765.2,3673.28 4781.87,3673.28 4781.87,3656.61 4765.2,3639.94 4781.87,3623.28 4781.87,3606.61 4765.2,3606.61 4748.53,3623.28 4731.87,3606.61 4715.2,3606.61 ; 4715.2,3823.28 4781.87,3823.28 4748.53,3756.61 4715.2,3823.28 ; 4715.2,3906.61 4781.87,3906.61 4781.87,3973.28 4715.2,3973.28 4715.2,3906.61 ; 4715.2,4206.61 4781.87,4206.61 4781.87,4273.28 4715.2,4273.28 4715.2,4206.61 ; 4715.2,4373.28 4731.87,4373.28 4731.87,4356.61 4765.2,4356.61 4765.2,4373.28 4781.87,4373.28 4781.87,4406.61 4765.2,4406.61 4765.2,4423.28 4731.87,4423.28 4731.87,4406.61 4715.2,4406.61 4715.2,4373.28 ; 4715.2,4539.94 4748.53,4506.61 4781.87,4539.94 4748.53,4573.28 4715.2,4539.94 ; 4728.53,4219.94 4768.53,4219.94 4768.53,4259.94 4728.53,4259.94 4728.53,4219.94
  lines w15: 4655.41,3411.61 10269.88,3411.61 ; 4655.41,4611.61 10269.88,4611.61 ; 5206.28,3261.61 5206.28,4761.61 ; 5796.13,3261.61 5796.13,4761.61 ; 6895.81,3261.61 6895.81,4761.61 ; 7401.68,3261.61 7401.68,4761.61 ; 8135.48,3261.61 8135.48,4761.61 ; 9635.04,3261.61 9635.04,4761.61 ; 4655.41,3261.61 10269.88,3261.61 10269.88,4761.61 4655.41,4761.61 4655.41,3261.61
  text "Symbol" at 4745.41,4656.61 h72
  text "Count" at 5251.28,4656.61 h72
  text "Hole Size" at 5841.13,4656.61 h72
  text "Plated" at 6940.81,4656.61 h72
  text "Hole Type" at 7446.68,4656.61 h72
  text "Drill Layer Pair" at 8180.48,4656.61 h72
  text "Via/Pad" at 9680.04,4656.61 h72
  text "5" at 5251.28,4506.61 h60
  text "7.87mil (0.200mm)" at 5841.13,4506.61 h60
  text "PTH" at 6940.81,4506.61 h60
  text "Round" at 7446.68,4506.61 h60
  text "Top Layer - Bottom Layer" at 8180.48,4506.61 h60
  text "Via" at 9680.04,4506.61 h60
  text "9" at 5251.28,4356.61 h60
  text "10.00mil (0.254mm)" at 5841.13,4356.61 h60
  text "PTH" at 6940.81,4356.61 h60
  text "Round" at 7446.68,4356.61 h60
  text "Top Layer - Bottom Layer" at 8180.48,4356.61 h60
  text "Via" at 9680.04,4356.61 h60
  text "83" at 5251.28,4206.61 h60
  text "12.00mil (0.305mm)" at 5841.13,4206.61 h60
  text "PTH" at 6940.81,4206.61 h60
  text "Round" at 7446.68,4206.61 h60
  text "Top Layer - Bottom Layer" at 8180.48,4206.61 h60
  text "Via" at 9680.04,4206.61 h60
  text "1" at 5251.28,4056.61 h60
  text "15.00mil (0.381mm)" at 5841.13,4056.61 h60
  text "PTH" at 6940.81,4056.61 h60
  text "Round" at 7446.68,4056.61 h60
  text "Top Layer - Bottom Layer" at 8180.48,4056.61 h60
  text "Via" at 9680.04,4056.61 h60
  text "6" at 5251.28,3906.61 h60
  text "20.00mil (0.508mm)" at 5841.13,3906.61 h60
  text "PTH" at 6940.81,3906.61 h60
  text "Round" at 7446.68,3906.61 h60
  text "Top Layer - Bottom Layer" at 8180.48,3906.61 h60
  text "Via" at 9680.04,3906.61 h60
  text "16" at 5251.28,3756.61 h60
  text "31.50mil (0.800mm)" at 5841.13,3756.61 h60
  text "PTH" at 6940.81,3756.61 h60
  text "Round" at 7446.68,3756.61 h60
  text "Top Layer - Bottom Layer" at 8180.48,3756.61 h60
  text "Pad" at 9680.04,3756.61 h60
  text "4" at 5251.28,3606.61 h60
  text "31.89mil (0.810mm)" at 5841.13,3606.61 h60
  text "PTH" at 6940.81,3606.61 h60
  text "Round" at 7446.68,3606.61 h60
  text "Top Layer - Bottom Layer" at 8180.48,3606.61 h60
  text "Pad" at 9680.04,3606.61 h60
  text "4" at 5251.28,3456.61 h60
  text "40.00mil (1.016mm)" at 5841.13,3456.61 h60
  text "PTH" at 6940.81,3456.61 h60
  text "Round" at 7446.68,3456.61 h60
  text "Top Layer - Bottom Layer" at 8180.48,3456.61 h60
  text "Pad" at 9680.04,3456.61 h60
  text "128 Total" at 5251.28,3306.61 h60
  text "FOR 7.87  MIL DRILL  +0/-7.87 MIL" at 5554.08,2890.63 h50
  text "TOLERANCE :-" at 4901.89,2884.79 h50
  text "FOR 10  MIL DRILL  +0/-10 MIL" at 5554.08,2800.23 h50
  text "FOR 12  MIL DRILL  +0/-12 MIL" at 5559.38,2715.31 h50
  text "FOR 20  MIL DRILL  +0/-20 MIL" at 5562.21,2626.98 h50
  text "FOR PTH +/- 3MIL" at 5552.42,2522.23 h50
  text ".Layer_Name" at 616.37,-839.1 h60
Mechanical 17:
  text ".Layer_Name" at 616.37,-839.1 h60
Mechanical 18:
  text ".Layer_Name" at 616.37,-839.1 h60
Mechanical 19:
  text ".Layer_Name" at 616.37,-839.1 h60

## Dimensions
0,0 to 0,1220.47 on M2 Board Dimensions
0,0 to 1141.73,0 on M2 Board Dimensions
39.37,-380.61 to 1039.37,-380.61 on M2 Board Dimensions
